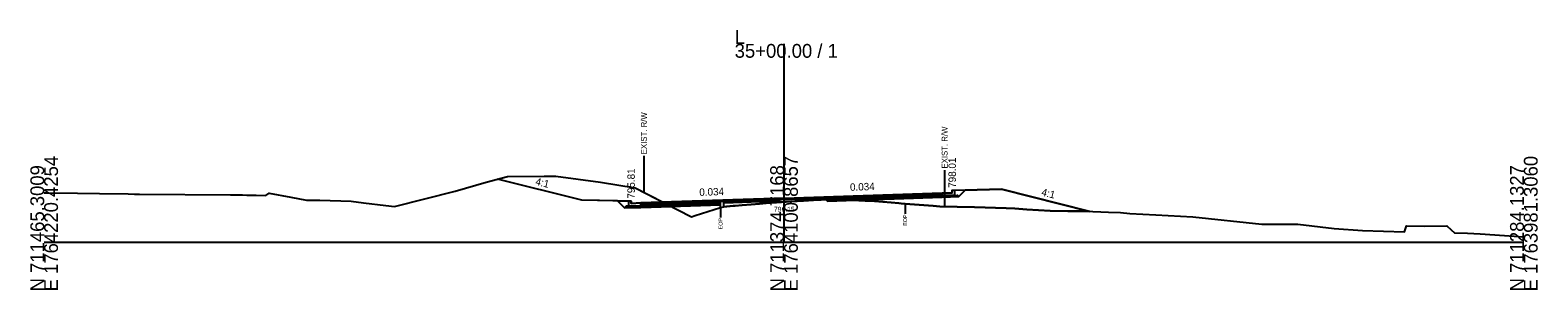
# Model space of a CAD drawing. Extents: x -26 to 5303, y -10 to 9578.
# Drawn here: x 1997.2 to 2302.8, y 4990.3 to 5043 of the extents above; entities that cross this region are included whole.
import ezdxf

# ---------------------------------------------------------------- set-up
doc = ezdxf.new("R2010")
doc.units = 0
for name, color, linetype in [('Default', 7, 'Continuous'), ('Exist CMT Pavement', 7, 'Continuous'), ('Exist Cross Section Cell', 7, 'Continuous'), ('Exist XS Ground Line', 7, 'Continuous'), ('Old_Level_10', 7, 'Continuous'), ('Old_Level_3', 7, 'Continuous'), ('Prop CMT Conc Surface', 7, 'Continuous'), ('Prop CMT Concrete Structures', 7, 'Continuous'), ('Prop CMT Pvmt Course 1', 7, 'Continuous'), ('Prop CMT Pvmt Course 1 CG', 7, 'Continuous'), ('Prop CMT Pvmt Course 2', 7, 'Continuous'), ('Prop CMT Pvmt Course 3', 7, 'Continuous'), ('Prop CMT Pvmt Surface', 7, 'Continuous'), ('Prop CMT Slope Grass', 7, 'Continuous'), ('Prop CMT Subgrade Earthwork', 7, 'Continuous'), ('Prop XS Earthwork Shape', 7, 'Continuous'), ('Prop XS Hydro Elevations', 7, 'Continuous'), ('Prop XS SE Text', 7, 'Continuous'), ('Prop XS Side Slope Text', 7, 'Continuous'), ('Prop XS Wedging', 7, 'Continuous')]:
    doc.layers.add(name, color=color, linetype=linetype)

msp = doc.modelspace()

# ---------------------------------------------------------------- linework, layer by layer
at = {"layer": 'Exist CMT Pavement'}
msp.add_lwpolyline([(2137.14, 5007.02), (2137.83, 5007.15), (2138.37, 5007.21), (2139.71, 5007.34), (2140.11, 5007.37), (2141.49, 5007.47), (2143.32, 5007.63), (2145.06, 5007.78), (2146.38, 5007.89), (2146.85, 5007.93), (2147.46, 5007.98), (2148.63, 5008.07), (2149.52, 5008.13), (2150, 5008.15), (2150.42, 5008.17), (2151.6, 5008.25), (2152.2, 5008.28), (2152.65, 5008.3), (2153.98, 5008.37), (2155.95, 5008.48), (2158.73, 5008.63)], dxfattribs=at)
at = {"layer": 'Exist Cross Section Cell'}
for p, q in [((2150, 5000), (2150, 5040.19)), ((2000, 5000), (2150, 5000)), ((2150, 5000), (2300, 5000))]:
    msp.add_line(p, q, dxfattribs=at)
at = {"layer": 'Exist XS Ground Line'}
msp.add_lwpolyline([(2000, 5010), (2000.46, 5009.99), (2006.79, 5009.9), (2011.2, 5009.83), (2017.02, 5009.76), (2018.34, 5009.74), (2019.34, 5009.74), (2037.81, 5009.58), (2040.23, 5009.56), (2041.08, 5009.55), (2043, 5009.51), (2044.95, 5009.43), (2045.6, 5009.93), (2050.01, 5009.12), (2053.18, 5008.53), (2055.88, 5008.47), (2062.22, 5008.3), (2064.73, 5007.94), (2069.28, 5007.41), (2071.05, 5007.2), (2083.33, 5010.32), (2089.62, 5012.16), (2093.97, 5013.31), (2101.37, 5013.4), (2103.72, 5013.37), (2112.82, 5012.16), (2119.82, 5011.03), (2128.49, 5006.57), (2131.27, 5005.1), (2131.98, 5005.36), (2137.14, 5007.02), (2137.83, 5007.15), (2139.71, 5007.34), (2140.11, 5007.37), (2141.49, 5007.47), (2143.32, 5007.63), (2145.06, 5007.78), (2146.38, 5007.89), (2146.85, 5007.93), (2147.46, 5007.98), (2149.52, 5008.13), (2150, 5008.15), (2150.42, 5008.17), (2151.6, 5008.25), (2152.2, 5008.28), (2152.65, 5008.3), (2153.98, 5008.37), (2155.79, 5008.47), (2157.55, 5008.57), (2158.93, 5008.64), (2159.34, 5008.65), (2159.88, 5008.66), (2161.12, 5008.66), (2162.06, 5008.62), (2162.91, 5008.58), (2164.02, 5008.52), (2164.69, 5008.49), (2165.2, 5008.46), (2166.48, 5008.39), (2168.34, 5008.27), (2170.05, 5008.15), (2171.71, 5008.02), (2173.29, 5007.88), (2173.77, 5007.82), (2174.54, 5007.75), (2180.24, 5007.32), (2181.58, 5007.23), (2188.6, 5007.1), (2195.01, 5006.88), (2196.81, 5006.81), (2199.2, 5006.62), (2203.95, 5006.33), (2207.56, 5006.29), (2211.09, 5006.27), (2215.76, 5006.07), (2218.23, 5006.01), (2220.1, 5005.8), (2225.37, 5005.53), (2232.86, 5005.15), (2246.88, 5003.66), (2254.2, 5003.6), (2261.54, 5002.78), (2267.32, 5002.34), (2275.81, 5002.06), (2276.2, 5003.27), (2279.78, 5003.22), (2284.37, 5003.27), (2285.28, 5002.47), (2285.94, 5001.88), (2288.61, 5001.78), (2291.14, 5001.68), (2300, 5001.06)], dxfattribs=at)
at = {"layer": 'Old_Level_10'}
for p, q in [((2121.6, 5017.52), (2121.6, 5010.12)), ((2182.56, 5014.62), (2182.56, 5007.21)), ((2174.54, 5007.75), (2174.54, 5005.7)), ((2137.14, 5007.02), (2137.14, 5004.97))]:
    msp.add_line(p, q, dxfattribs=at)
at = {"layer": 'Prop CMT Conc Surface'}
for points in [[(2184.1, 5010.01), (2184.1, 5010.51), (2184.6, 5010.51)], [(2119, 5007.81), (2118.99, 5008.31), (2118.49, 5008.31)], [(2121, 5007.95), (2119, 5007.81)], [(2182.1, 5010.02), (2184.1, 5010.01)]]:
    msp.add_lwpolyline(points, dxfattribs=at)
at = {"layer": 'Prop CMT Concrete Structures'}
for points in [[(2182.1, 5010.02), (2184.1, 5010.01), (2184.1, 5010.51), (2184.6, 5010.51)], [(2184.6, 5010.51), (2184.6, 5009.52), (2182.1, 5009.44)], [(2121, 5007.95), (2119, 5007.81), (2118.99, 5008.31), (2118.49, 5008.31)], [(2118.49, 5008.31), (2118.5, 5007.29), (2121, 5007.37)], [(2121, 5007.37), (2121, 5007.95)], [(2182.1, 5009.44), (2182.1, 5010.02)]]:
    msp.add_lwpolyline(points, dxfattribs=at)
at = {"layer": 'Prop CMT Pvmt Course 1'}
for points in [[(2150, 5008.94), (2121, 5007.95)], [(2121, 5007.7), (2137.14, 5008.25)], [(2121, 5007.95), (2121, 5007.7)], [(2137.14, 5008.25), (2150, 5008.69)], [(2137.14, 5008.25), (2137.14, 5008.25)], [(2150, 5008.94), (2182.1, 5010.02)], [(2158.73, 5008.98), (2150, 5008.69)], [(2150, 5008.69), (2150, 5008.94)], [(2150, 5008.69), (2150, 5008.69), (2150, 5008.69)], [(2182.1, 5009.77), (2158.73, 5008.98)], [(2158.73, 5008.98), (2158.73, 5008.98)], [(2182.1, 5010.02), (2182.1, 5009.77)]]:
    msp.add_lwpolyline(points, dxfattribs=at)
at = {"layer": 'Prop CMT Pvmt Course 1 CG'}
for points in [[(2121, 5007.37), (2118, 5007.27), (2117.65, 5006.92)], [(2121, 5007.04), (2121, 5007.37)], [(2182.1, 5009.44), (2185.1, 5009.54), (2185.43, 5009.22)], [(2182.1, 5009.11), (2182.1, 5009.44)], [(2185.43, 5009.22), (2182.1, 5009.11)], [(2117.65, 5006.92), (2121, 5007.04)]]:
    msp.add_lwpolyline(points, dxfattribs=at)
at = {"layer": 'Prop CMT Pvmt Course 2'}
for points in [[(2137.14, 5008.25), (2121, 5007.7)], [(2121, 5007.37), (2137.14, 5007.92)], [(2121, 5007.7), (2121, 5007.37)], [(2137.14, 5007.92), (2137.14, 5008.25)], [(2158.73, 5008.98), (2182.1, 5009.77)], [(2182.1, 5009.44), (2158.73, 5008.65)], [(2158.73, 5008.65), (2158.73, 5008.98)], [(2182.1, 5009.77), (2182.1, 5009.44)]]:
    msp.add_lwpolyline(points, dxfattribs=at)
at = {"layer": 'Prop CMT Pvmt Course 3'}
for points in [[(2137.14, 5007.92), (2121, 5007.37)], [(2121, 5007.04), (2137.14, 5007.58)], [(2121, 5007.37), (2121, 5007.04)], [(2137.14, 5007.58), (2137.14, 5007.92)], [(2158.73, 5008.65), (2182.1, 5009.44)], [(2182.1, 5009.11), (2158.73, 5008.31)], [(2158.73, 5008.31), (2158.73, 5008.65)], [(2182.1, 5009.44), (2182.1, 5009.11)]]:
    msp.add_lwpolyline(points, dxfattribs=at)
at = {"layer": 'Prop CMT Pvmt Surface'}
for points in [[(2150, 5008.94), (2121, 5007.95)], [(2150, 5008.94), (2182.1, 5010.02)]]:
    msp.add_lwpolyline(points, dxfattribs=at)
at = {"layer": 'Prop CMT Slope Grass'}
for points in [[(2118.49, 5008.31), (2108.99, 5008.5), (2091.92, 5012.77)], [(2184.6, 5010.51), (2194.1, 5010.7), (2211.99, 5006.23)]]:
    msp.add_lwpolyline(points, dxfattribs=at)
at = {"layer": 'Prop CMT Subgrade Earthwork'}
for p, q in [((2137.14, 5007.02), (2137.14, 5007.58)), ((2158.73, 5008.31), (2158.73, 5008.63))]:
    msp.add_line(p, q, dxfattribs=at)
for points in [[(2182.1, 5009.11), (2185.43, 5009.22), (2186.76, 5010.55)], [(2121, 5007.04), (2117.65, 5006.92), (2116.22, 5008.35)], [(2137.14, 5007.58), (2121, 5007.04)], [(2158.73, 5008.31), (2182.1, 5009.11)]]:
    msp.add_lwpolyline(points, dxfattribs=at)
at = {"layer": 'Prop XS Earthwork Shape'}
for points in [[(2119.82, 5011.03), (2125.51, 5008.11), (2121, 5007.95), (2119, 5007.81), (2118.99, 5008.31), (2118.49, 5008.31), (2116.22, 5008.35), (2108.99, 5008.5), (2091.92, 5012.77), (2093.97, 5013.31), (2101.37, 5013.4), (2103.72, 5013.37), (2112.82, 5012.16)], [(2118.99, 5008.31), (2118.49, 5008.31), (2116.22, 5008.35), (2108.99, 5008.5), (2091.92, 5012.77), (2093.97, 5013.31), (2101.37, 5013.4), (2103.72, 5013.37), (2112.82, 5012.16), (2119.82, 5011.03), (2125.51, 5008.11), (2121, 5007.95), (2119, 5007.81)], [(2164.39, 5008.51), (2182.1, 5009.11), (2185.43, 5009.22), (2186.76, 5010.55), (2194.1, 5010.7), (2211.99, 5006.23), (2211.09, 5006.27), (2207.56, 5006.29), (2203.95, 5006.33), (2199.2, 5006.62), (2196.81, 5006.81), (2195.01, 5006.88), (2188.6, 5007.1), (2181.58, 5007.23), (2180.24, 5007.32), (2174.54, 5007.75), (2173.77, 5007.82), (2173.29, 5007.88), (2171.71, 5008.02), (2170.05, 5008.15), (2168.34, 5008.27), (2166.48, 5008.39), (2165.2, 5008.46), (2164.69, 5008.49)], [(2188.6, 5007.1), (2195.01, 5006.88), (2196.81, 5006.81), (2199.2, 5006.62), (2203.95, 5006.33), (2207.56, 5006.29), (2211.09, 5006.27), (2211.99, 5006.23), (2194.1, 5010.7), (2186.76, 5010.55), (2185.43, 5009.22), (2182.1, 5009.11), (2164.39, 5008.51), (2164.69, 5008.49), (2165.2, 5008.46), (2166.48, 5008.39), (2168.34, 5008.27), (2170.05, 5008.15), (2171.71, 5008.02), (2173.29, 5007.88), (2173.77, 5007.82), (2174.54, 5007.75), (2180.24, 5007.32), (2181.58, 5007.23)], [(2127.19, 5007.25), (2121, 5007.04), (2117.65, 5006.92), (2116.22, 5008.35), (2118.49, 5008.31), (2118.99, 5008.31), (2119, 5007.81), (2121, 5007.95), (2125.51, 5008.11)], [(2118.99, 5008.31), (2118.49, 5008.31), (2116.22, 5008.35), (2117.65, 5006.92), (2121, 5007.04), (2127.19, 5007.25), (2125.51, 5008.11), (2121, 5007.95), (2119, 5007.81)], [(2127.19, 5007.25), (2128.49, 5006.57), (2131.27, 5005.1), (2131.98, 5005.36), (2137.14, 5007.02), (2137.14, 5007.58)], [(2137.14, 5007.58), (2127.19, 5007.25), (2128.49, 5006.57), (2131.27, 5005.1), (2131.98, 5005.36), (2137.14, 5007.02)], [(2158.73, 5008.31), (2158.73, 5008.63), (2158.93, 5008.64), (2159.88, 5008.66), (2161.12, 5008.66), (2162.06, 5008.62), (2162.91, 5008.58), (2164.02, 5008.52), (2164.39, 5008.51)]]:
    msp.add_lwpolyline(points, close=True, dxfattribs=at)
at = {"layer": 'Prop XS Wedging'}
for points in [[(2137.83, 5007.15), (2137.83, 5008.34), (2138.37, 5008.36), (2139.71, 5008.39), (2140.11, 5008.41), (2141.49, 5008.44), (2143.32, 5008.5), (2145.06, 5008.55), (2146.38, 5008.58), (2146.85, 5008.6), (2147.46, 5008.61), (2148.63, 5008.65), (2149.52, 5008.67), (2150, 5008.69), (2150.42, 5008.7), (2151.6, 5008.73), (2152.2, 5008.75), (2152.65, 5008.76), (2153.99, 5008.8), (2155.95, 5008.85), (2158.93, 5008.94), (2158.93, 5008.64), (2155.95, 5008.48), (2153.99, 5008.36), (2152.65, 5008.3), (2152.2, 5008.28), (2151.6, 5008.25), (2150.42, 5008.17), (2150, 5008.15), (2149.52, 5008.13), (2148.63, 5008.07), (2147.46, 5007.98), (2146.85, 5007.94), (2146.38, 5007.89), (2145.06, 5007.78), (2143.32, 5007.63), (2141.49, 5007.47), (2140.11, 5007.37), (2139.71, 5007.34), (2138.37, 5007.21)], [(2137.83, 5007.15), (2137.83, 5008.01), (2138.37, 5008.03), (2139.71, 5008.06), (2140.11, 5008.08), (2141.49, 5008.11), (2143.32, 5008.17), (2145.06, 5008.22), (2146.38, 5008.25), (2146.85, 5008.27), (2147.46, 5008.28), (2148.51, 5008.31), (2148.75, 5008.08), (2147.46, 5007.98), (2146.85, 5007.94), (2146.38, 5007.89), (2145.06, 5007.78), (2143.32, 5007.63), (2141.49, 5007.47), (2140.11, 5007.37), (2139.71, 5007.34), (2138.37, 5007.21)]]:
    msp.add_lwpolyline(points, close=True, dxfattribs=at)

# ---------------------------------------------------------------- texts
at = {"layer": 'Default'}
msp.add_text('-', height=0.0001, dxfattribs=at).set_placement((2000, 5000))
at = {"layer": 'Exist Cross Section Cell'}
for s, p in [('L', (2140, 5040.19)), ('35+00.00 / 1', (2140, 5037.39))]:
    msp.add_text(s, height=2.8, dxfattribs=at).set_placement(p)
for s, p in [('E 1764220.4254', (2002.8, 4990)), ('E 1764100.8657', (2152.8, 4990)), ('E 1763981.3060', (2302.8, 4990)), ('N 711465.3009', (2000, 4990)), ('N 711374.7168', (2150, 4990)), ('N 711284.1327', (2300, 4990))]:
    msp.add_text(s, height=2.8, rotation=90, dxfattribs=at).set_placement(p)
at = {"layer": 'Old_Level_10'}
for s, height, p in [('EXIST. R/W', 1.181, (2122.19, 5017.82)), ('EXIST. R/W', 1.181, (2183.15, 5014.92)), ('EOP', 0.787, (2137.53, 5002.58)), ('EOP', 0.787, (2174.94, 5003.3))]:
    msp.add_text(s, height=height, rotation=90, dxfattribs=at).set_placement(p)
at = {"layer": 'Old_Level_3'}
msp.add_text('796.15', height=1, dxfattribs=at).set_placement((2147.95, 5006.15))
at = {"layer": 'Prop XS Hydro Elevations'}
for s, p in [('798.01', (2184.85, 5011.01)), ('795.81', (2119.75, 5008.81))]:
    msp.add_text(s, height=1.5, rotation=90, dxfattribs=at).set_placement(p)
at = {"layer": 'Prop XS SE Text'}
for p in [(2132.85, 5009.36), (2163.4, 5010.39)]:
    msp.add_text('0.034', height=1.5, rotation=1.9393, dxfattribs=at).set_placement(p)
at = {"layer": 'Prop XS Side Slope Text'}
for p in [(2099.48, 5011.65), (2202.07, 5009.48)]:
    msp.add_text('4:1', height=1.5, rotation=345.9638, dxfattribs=at).set_placement(p)

doc.saveas('drawing.dxf')
